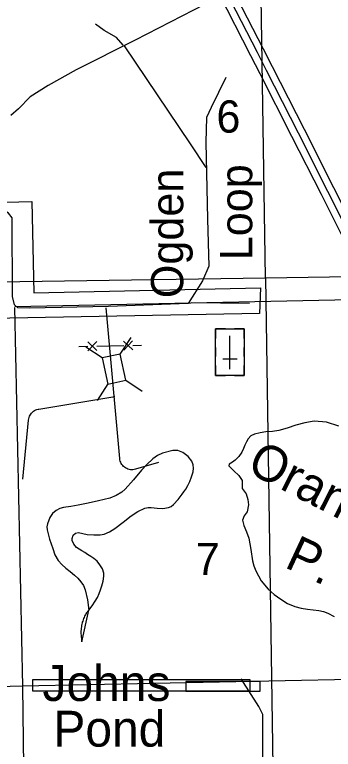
# Model space of a CAD drawing. Extents: x 2480962 to 2688785, y 277103 to 599240.
# Drawn here: x 2517578 to 2522023, y 452337 to 462587 of the extents above; entities that cross this region are included whole.
import ezdxf

# ---------------------------------------------------------------- set-up
doc = ezdxf.new("R2010")
doc.units = 0
for name, color, linetype in [('County Routes Highway Center Lines', 7, 'Continuous'), ('Culture', 7, 'Continuous'), ('Divided_Highway', 7, 'Continuous'), ('Interstate Divided Highway Outline and Fill', 7, 'Continuous'), ('Interstate Highway Center Lines', 7, 'Continuous'), ('Lakes and Ponds', 7, 'Continuous'), ('Lakes and Ponds Text', 7, 'Continuous'), ('Level 31', 7, 'Continuous'), ('Level 36', 7, 'Continuous'), ('Level 42', 7, 'Continuous'), ('Local Roads Improved', 7, 'Continuous'), ('Local Roads Related Text', 7, 'Continuous'), ('Local Roads Unimproved', 7, 'Continuous'), ('Section Lines', 7, 'Continuous'), ('Section Numbers', 7, 'Continuous'), ('Swamps', 7, 'Continuous'), ('Township and Range lines', 7, 'Continuous'), ('Uninventoried Roads and Features', 7, 'Continuous')]:
    doc.layers.add(name, color=color, linetype=linetype)

msp = doc.modelspace()

# ---------------------------------------------------------------- linework, layer by layer
at = {"layer": 'County Routes Highway Center Lines'}
msp.add_lwpolyline([(2520234.373, 462732.633), (2519257.456, 462232.681), (2518435.696, 461818.928), (2518044.929, 461600.558), (2517792.079, 461439.654), (2517631.175, 461273.003), (2517521.99, 461181.058)], dxfattribs=at)
at = {"layer": 'Culture'}
for p, q in [((2520518.626, 458204.77), (2520381.126, 458204.77)), ((2520381.126, 458204.77), (2520381.126, 458067.27)), ((2520781.126, 458204.77), (2520643.626, 458204.77)), ((2520781.126, 458067.27), (2520781.126, 458204.77)), ((2520581.126, 457642.27), (2520581.126, 458104.77)), ((2520381.126, 457942.27), (2520381.126, 457817.27)), ((2520781.126, 457817.27), (2520781.126, 457942.27)), ((2520381.126, 457692.27), (2520381.126, 457554.77)), ((2520681.126, 457779.77), (2520481.126, 457779.77)), ((2520781.126, 457554.77), (2520781.126, 457692.27)), ((2520381.126, 457554.77), (2520518.626, 457554.77)), ((2520643.626, 457554.77), (2520781.126, 457554.77))]:
    msp.add_line(p, q, dxfattribs=at)
msp.add_lwpolyline([(2520781.126, 457554.77), (2520381.126, 457554.77), (2520381.126, 458204.77), (2520781.126, 458204.77)], close=True, dxfattribs=at)
at = {"layer": 'Divided_Highway'}
for p, q in [((2521075.087, 458914.627), (2520376.685, 504368.593)), ((2521075.087, 458914.627), (2560538.616, 459542.689)), ((2481610.945, 458329.771), (2521075.087, 458914.627)), ((2521075.087, 458914.627), (2521773.243, 413460.785))]:
    msp.add_line(p, q, dxfattribs=at)
at = {"layer": 'Interstate Divided Highway Outline and Fill'}
for points in [[(2528901.11, 451854.171), (2528268.057, 452341.135), (2527920.39, 452614.07), (2527364.656, 453039.807), (2526786.62, 453487.948), (2526312.207, 453855.131), (2525944.896, 454137.927), (2525724.449, 454306.505), (2525344.576, 454605.896), (2525009.188, 454912.536), (2524757.518, 455183.321), (2524529.895, 455462.239), (2524332.601, 455719.994), (2524105.854, 456090.454), (2524003.576, 456275.833), (2523880.98, 456511.346), (2523540.143, 457186.528), (2523013.836, 458226.147), (2522581.872, 459077.083), (2522032.87, 460171.839), (2521620.171, 460984.24), (2521175.154, 461858.031), (2521048.429, 462108.233), (2520603.558, 462978.49)], [(2520424.96, 462888.467), (2520870.178, 462017.531), (2520996.835, 461767.464), (2521441.906, 460893.566), (2521854.324, 460081.72), (2522403.313, 458986.99), (2522835.449, 458135.715), (2523361.654, 457096.297), (2523703.001, 456420.105), (2523827.291, 456181.338), (2523932.916, 455989.891), (2524167.455, 455606.701), (2524372.974, 455338.2), (2524606.638, 455051.88), (2524868.23, 454770.42), (2525215.026, 454453.35), (2525601.798, 454148.521), (2525823.146, 453979.255), (2526189.995, 453696.813), (2526664.142, 453329.836), (2527242.57, 452881.392), (2527797.822, 452456.024), (2528145.333, 452183.212)]]:
    msp.add_lwpolyline(points, dxfattribs=at)
at = {"layer": 'Interstate Highway Center Lines'}
msp.add_lwpolyline([(2520514.259, 462933.478), (2520959.303, 462062.882), (2521085.994, 461812.748), (2521531.038, 460938.903), (2521943.597, 460126.779), (2522492.593, 459032.036), (2522924.642, 458180.931), (2523450.899, 457141.413), (2523791.99, 456465.726), (2523915.433, 456228.586), (2524019.385, 456040.173), (2524250.028, 455663.347), (2524451.435, 455400.219), (2524682.078, 455117.6), (2524938.709, 454841.478), (2525279.801, 454529.623), (2525663.123, 454227.513), (2525884.021, 454058.591), (2526251.101, 453775.972), (2526725.381, 453408.892), (2527303.613, 452960.6), (2527859.106, 452535.047), (2528206.695, 452262.174)], dxfattribs=at)
at = {"layer": 'Lakes and Ponds'}
msp.add_line((2518515.369, 453835.224), (2518612.207, 454277.849), dxfattribs=at)
for points in [[(2522101.225, 456845.463), (2521928.911, 456901.988), (2521756.617, 456913.424), (2521627.566, 456893.02), (2521498.558, 456861.487), (2521380.401, 456819.855), (2521262.07, 456783.532), (2521172.613, 456772.79), (2521082.723, 456764.615), (2521003.419, 456752.734), (2520924.683, 456735.507), (2520874.369, 456711.427), (2520835.934, 456670.65), (2520811.271, 456625.893), (2520789.887, 456580.138), (2520769.977, 456532.193), (2520749.212, 456484.442), (2520707.037, 456424.737), (2520655.974, 456372.008), (2520614.473, 456345.207), (2520572.332, 456317.793), (2520567.489, 456291.321), (2520635.389, 456224.471), (2520707.13, 456156.505), (2520750.536, 456088.643), (2520752.331, 456033.188), (2520752.386, 455977.845), (2520806.535, 455899.611), (2520831.072, 455823.49), (2520840.786, 455747.15), (2520821.241, 455651.816), (2520780.031, 455592.66), (2520754.504, 455534.561), (2520776.868, 455461.059), (2520811.111, 455372.183), (2520843.257, 455282.762), (2520872.588, 455125.751), (2520896.086, 454967.013), (2520915.105, 454895.398), (2520940.727, 454825.286), (2521014.942, 454689.713), (2521114.089, 454569.664), (2521198.621, 454494.71), (2521290.797, 454430.208), (2521386.226, 454371.547), (2521488.019, 454328.047), (2521575.096, 454308.154), (2521662.965, 454294.114), (2521742.392, 454285.23), (2521821.798, 454275.735), (2521886.563, 454260.095), (2521949.288, 454235.707), (2522035.347, 454189.192)], [(2518612.207, 454277.849), (2518659.223, 454338.9), (2518701.401, 454403.129), (2518731.596, 454455.361), (2518757.749, 454509.651), (2518776.721, 454562.2), (2518792.966, 454615.809), (2518811.267, 454684.564), (2518822.371, 454753.533), (2518820.634, 454793.913), (2518801, 454853.317), (2518766.902, 454910.907), (2518727.07, 454960.314), (2518680.881, 454999.147), (2518638.265, 455027.686), (2518595.389, 455055.731), (2518555.336, 455081.446), (2518515.267, 455107.128), (2518477.952, 455129.633), (2518440.517, 455153.342), (2518400.905, 455198.975), (2518380.734, 455252.588), (2518379.997, 455279.545), (2518394.267, 455322.629), (2518426.603, 455353.652), (2518467.52, 455362.033), (2518529.016, 455349.379), (2518590.72, 455335.365), (2518680.67, 455328.801), (2518770.507, 455327.902), (2518824.771, 455337.709), (2518902.062, 455370.742), (2518975.122, 455415.863), (2519090.791, 455504.682), (2519204.653, 455593.973), (2519294.264, 455655.266), (2519393.068, 455702.766), (2519437.924, 455709.799), (2519482.786, 455709.587), (2519564.802, 455702.296), (2519646.813, 455696.575), (2519725.107, 455710.352), (2519761.566, 455727.082), (2519793.848, 455751.881), (2519856.805, 455822.898), (2519912.971, 455896.426), (2519939.22, 455930.841), (2519964.653, 455965.924), (2519995.136, 456017.723), (2520021.001, 456072.445), (2520046.467, 456140.797), (2520066.254, 456210.442), (2520074.424, 456257.745), (2520069.951, 456305.503), (2520048.718, 456356.979), (2519996.58, 456422.349), (2519924.411, 456477.161), (2519855.342, 456505.169), (2519786.532, 456506.455), (2519638.984, 456469.4), (2519568.016, 456436.679), (2519503.117, 456390.749), (2519421.838, 456311.386), (2519347.279, 456229.741), (2519234.861, 456097.808), (2519119.158, 455967.213), (2519071.982, 455925.677), (2518992.036, 455876.206), (2518904.594, 455842.138), (2518825.96, 455820.686), (2518746.73, 455802.478), (2518604.589, 455773.271), (2518462.346, 455744.811), (2518359.693, 455726.933), (2518256.85, 455709.61), (2518205.864, 455695.149), (2518157.096, 455670.951), (2518106.338, 455627.111), (2518068.963, 455569.16), (2518034.655, 455484.281), (2518027.501, 455441.741), (2518029.521, 455399.598), (2518061.79, 455268.117), (2518107.884, 455137.064), (2518140.076, 455049.883), (2518184.66, 454969.502), (2518236.089, 454914.792), (2518292.077, 454865.797), (2518351.09, 454816.763), (2518409.969, 454767.55), (2518457.261, 454722.851), (2518501.361, 454674.124), (2518537.66, 454622.273), (2518561.321, 454564.326), (2518592.411, 454422.877), (2518613.622, 454280.234)], [(2518613.622, 454280.234), (2518603.08, 454270.269), (2518593.155, 454259.319), (2518586.875, 454251.528), (2518578.912, 454240.596), (2518569.006, 454225.179), (2518563.702, 454216.005), (2518557.952, 454205.249), (2518551.778, 454192.672), (2518545.23, 454178.02), (2518538.392, 454161.056), (2518531.39, 454141.601), (2518526.165, 454125.723), (2518521.365, 454109.894), (2518518.452, 454099.308), (2518514.986, 454085.082), (2518513.247, 454076.865), (2518511.493, 454067.372), (2518508.428, 454048.024), (2518505.875, 454028.673), (2518504.513, 454015.772), (2518503.185, 453998.568), (2518502.703, 453988.735), (2518502.425, 453977.496), (2518502.603, 453950.696), (2518503.779, 453923.885), (2518505.14, 453906.009), (2518507.702, 453882.176), (2518509.562, 453868.558), (2518512.047, 453852.999), (2518515.369, 453835.224)]]:
    msp.add_lwpolyline(points, dxfattribs=at)
at = {"layer": 'Level 31'}
for points in [[(2520992.255, 458420.211), (2517258.316, 458348.68), (2517244.009, 459707.776), (2517272.622, 459965.29), (2517816.261, 459979.596), (2517844.873, 458706.337), (2521006.561, 458777.868)], [(2517832.967, 453312.156), (2520859.632, 453312.156), (2520859.632, 453148.129), (2517832.967, 453148.129)], [(2521002.559, 453284.856), (2519965.838, 453284.856), (2519965.838, 453148.354), (2521002.559, 453148.354)]]:
    msp.add_lwpolyline(points, close=True, dxfattribs=at)
at = {"layer": 'Local Roads Improved'}
for points in [[(2519089.623, 462162.277), (2518999.467, 462268.825), (2518827.352, 462367.176), (2518704.413, 462457.332)], [(2519106.015, 462154.081), (2520023.964, 460785.354), (2520245.255, 460457.516)], [(2520523.918, 461711.499), (2520319.019, 461293.504), (2520253.451, 461154.173), (2520245.255, 460809.942), (2520269.843, 459736.27), (2520286.235, 459080.593), (2520196.079, 458875.693), (2519999.376, 458556.051), (2518884.724, 458515.071), (2517786.464, 458490.483), (2517622.545, 458498.679), (2517573.369, 458539.659), (2517548.781, 458654.402), (2517540.585, 459752.662), (2517491.409, 459818.23), (2517442.233, 459851.014), (2516491.501, 459842.818)], [(2520934.587, 448525.89), (2521024.744, 450107.743), (2521041.136, 451722.381), (2521041.136, 452820.663), (2520983.763, 452935.409), (2520737.879, 453320.627)]]:
    msp.add_lwpolyline(points, dxfattribs=at)
at = {"layer": 'Local Roads Unimproved'}
msp.add_line((2520040.356, 458572.443), (2520851.757, 458564.247), dxfattribs=at)
at = {"layer": 'Section Lines'}
for p, q in [((2517577.752, 458514.766), (2523010.878, 458628.006)), ((2523099.082, 453327.36), (2517688.26, 453216.366)), ((2517692.193, 453216.442), (2512209.867, 453109.628))]:
    msp.add_line(p, q, dxfattribs=at)
at = {"layer": 'Swamps'}
msp.add_line((2517692.193, 453216.443), (2517688.26, 453216.366), dxfattribs=at)
at = {"layer": 'Township and Range lines'}
for p, q in [((2517692.193, 453216.442), (2517577.939, 458500.67)), ((2517753.341, 447881.157), (2517692.238, 453214.359))]:
    msp.add_line(p, q, dxfattribs=at)
at = {"layer": 'Uninventoried Roads and Features'}
for p, q in [((2519044.686, 456392.624), (2518854.965, 458498.716)), ((2518598.261, 458024.238), (2518725.307, 457901.317)), ((2518723.244, 458026.301), (2518600.324, 457899.255)), ((2519050.446, 457852.717), (2519200.64, 458083.026)), ((2519098.194, 458032.489), (2519225.24, 457909.569)), ((2519223.177, 458034.552), (2519100.257, 457907.506)), ((2518474.309, 457959.683), (2518599.292, 457961.746)), ((2518799.938, 457799.972), (2518569.628, 457950.167)), ((2518724.276, 457963.809), (2519099.225, 457969.998)), ((2519224.208, 457972.061), (2519349.192, 457974.123)), ((2519050.446, 457852.717), (2518799.938, 457799.972)), ((2518799.938, 457799.972), (2518877.2, 457433.017)), ((2519127.708, 457485.762), (2519050.446, 457852.717)), ((2518877.2, 457433.017), (2519127.708, 457485.762)), ((2519127.708, 457485.761), (2519358.017, 457335.567)), ((2518878.237, 457434.607), (2518728.042, 457204.298)), ((2517914.107, 457084.693), (2518974.102, 457258.824)), ((2517691.546, 456107.796), (2517771.056, 456931.775)), ((2519585.576, 456338.771), (2519263.167, 456243.959))]:
    msp.add_line(p, q, dxfattribs=at)
for points in [[(2517771.056, 456931.775), (2517773.715, 456949.547), (2517778.217, 456966.944), (2517784.514, 456983.774), (2517792.535, 456999.855), (2517802.194, 457015.008), (2517813.382, 457029.068), (2517825.98, 457041.883), (2517839.848, 457053.31), (2517854.834, 457063.226), (2517870.775, 457071.52), (2517887.496, 457078.103), (2517904.811, 457082.901), (2517914.107, 457084.693)], [(2519263.167, 456243.959), (2519245.76, 456239.817), (2519228.015, 456237.517), (2519210.127, 456237.083), (2519192.292, 456238.522), (2519174.705, 456241.818), (2519157.559, 456246.934), (2519141.041, 456253.814), (2519125.334, 456262.383), (2519110.608, 456272.547), (2519097.025, 456284.195), (2519084.734, 456297.199), (2519073.87, 456311.416), (2519064.551, 456326.691), (2519056.88, 456342.858), (2519050.941, 456359.737), (2519046.799, 456377.144), (2519044.686, 456392.624)]]:
    msp.add_lwpolyline(points, dxfattribs=at)

# ---------------------------------------------------------------- texts
at = {"layer": 'Lakes and Ponds Text'}
msp.add_text('Johns ', height=500, rotation=359.9981611, dxfattribs=at).set_placement((2517966.562, 453011.092))
msp.add_text('Pond', height=500, dxfattribs=at).set_placement((2518117.953, 452374.434))
at = {"layer": 'Level 36'}
msp.add_text('6', height=450, rotation=359.9795306, dxfattribs=at).set_placement((2520392.712, 460941.64))
at = {"layer": 'Level 42'}
for s, rotation, p in [('Orange', 332.9503389, (2520796.942, 456217.226)), ('P.', 335.0046139, (2521327.051, 454883.408))]:
    msp.add_text(s, height=500, rotation=rotation, dxfattribs=at).set_placement(p)
at = {"layer": 'Local Roads Related Text'}
for s, rotation, p in [('Loop', 90.0008667, (2520892.28, 459161.102)), ('Ogden', 90.0008694, (2519929.381, 458631.985))]:
    msp.add_text(s, height=450, rotation=rotation, dxfattribs=at).set_placement(p)
at = {"layer": 'Section Numbers'}
msp.add_text('7', height=450, rotation=359.9795472, dxfattribs=at).set_placement((2520103.03, 454767.628))

doc.saveas('drawing.dxf')
